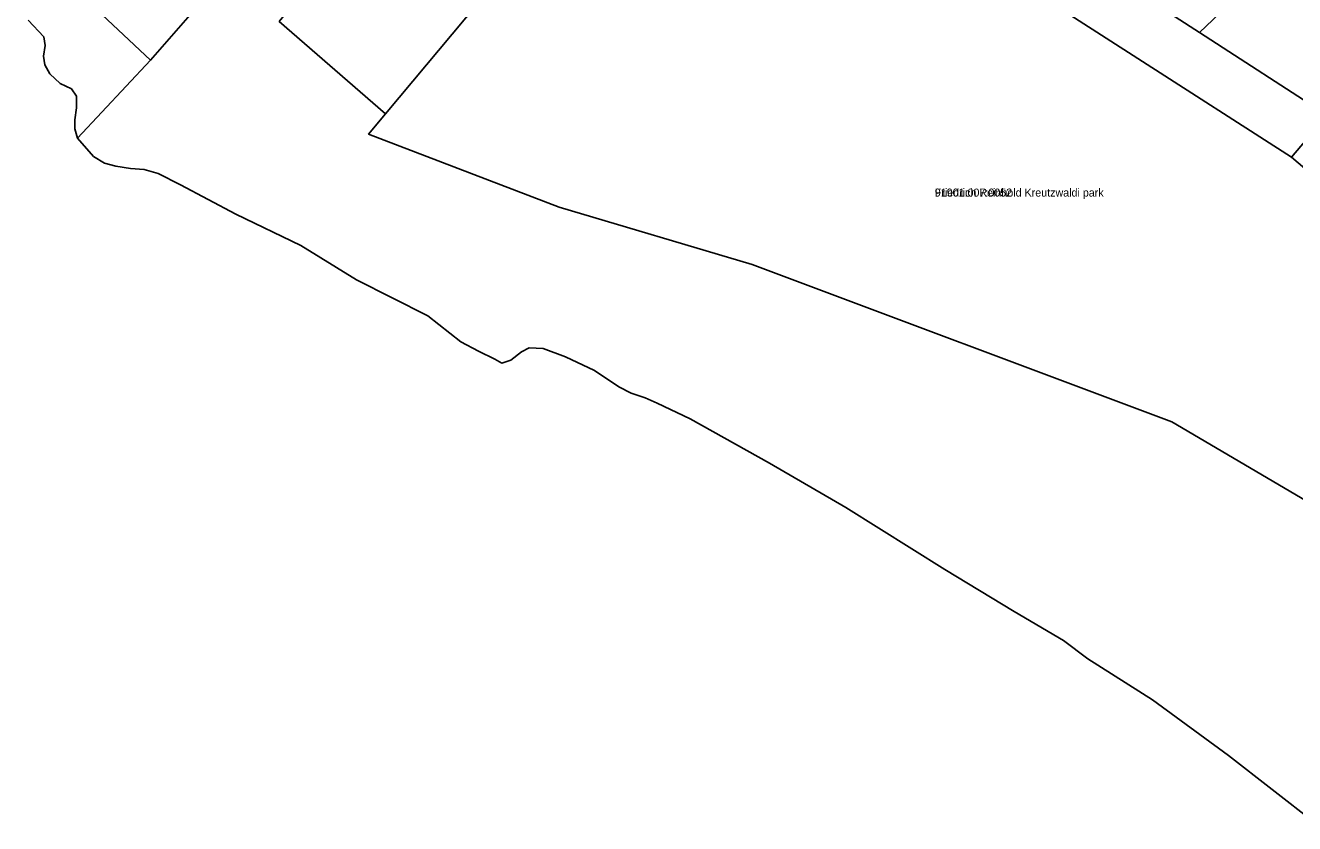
# Model space of a CAD drawing. Extents: x 675810 to 681273, y 6411190 to 6417565.
# Drawn here: x 677270.4 to 677508.4, y 6415331.4 to 6415481 of the extents above; entities that cross this region are included whole.
import ezdxf

# ---------------------------------------------------------------- set-up
doc = ezdxf.new("R2010")
doc.units = 0
for name, color, linetype in [('L_AADRESS', 7, 'Continuous'), ('PIIR', 7, 'Continuous'), ('TUNNUS', 7, 'Continuous')]:
    doc.layers.add(name, color=color, linetype=linetype)

msp = doc.modelspace()

# ---------------------------------------------------------------- linework, layer by layer
at = {"layer": 'PIIR'}
for points in [[(677619.3, 6415586.7), (677640.22, 6415568.39), (677619.9, 6415544.86), (677604, 6415528.75), (677527.68, 6415439.36), (677507.74, 6415456.28), (677514.44, 6415464.15), (677541.32, 6415495.69), (677551.91, 6415508.21), (677567.84, 6415526.77), (677572.82, 6415532.42), (677579.26, 6415540.06), (677605.9, 6415571.07)], [(677377.21, 6415550.75), (677395.17, 6415538.44), (677460.53, 6415498.36), (677473.16, 6415490.87), (677490.51, 6415479.64), (677514.44, 6415464.15), (677507.74, 6415456.28), (677392.53, 6415530.33), (677391.54, 6415531.46), (677372.02, 6415544.64)], [(677473.16, 6415490.87), (677508.91, 6415532.58), (677514.96, 6415526.92), (677510.82, 6415522.1), (677523.55, 6415511.07), (677490.51, 6415479.64)], [(677274.63, 6415492.53), (677270.38, 6415496.45), (677303.25, 6415531.9), (677313.36, 6415522.9), (677315.6, 6415520.9), (677301.23, 6415503.97), (677302.65, 6415496.91), (677308.39, 6415492.05), (677307.59, 6415490.8), (677306.11, 6415488.49), (677293.83, 6415474.44)], [(677392.53, 6415530.33), (677507.74, 6415456.28), (677527.68, 6415439.36), (677550.13, 6415420.31), (677564.99, 6415407.75), (677582.2, 6415400.99), (677554.69, 6415367.45), (677550.88, 6415368.11), (677485.36, 6415406.68), (677406.64, 6415436.15), (677370.49, 6415446.92), (677334.72, 6415460.59), (677337.9, 6415464.39), (677355.53, 6415485.48), (677358.99, 6415489.69), (677380.91, 6415516.25)], [(677490.51, 6415479.64), (677523.55, 6415511.07), (677541.32, 6415495.69), (677514.44, 6415464.15)], [(677334.97, 6415502.53), (677355.53, 6415485.48), (677337.9, 6415464.39), (677317.98, 6415481.72)]]:
    msp.add_lwpolyline(points, close=True, dxfattribs=at)
for points in [[(677274.63, 6415492.53), (677293.83, 6415474.44), (677280.17, 6415459.81), (677279.66, 6415461.59), (677279.64, 6415463.28), (677279.97, 6415465.54), (677279.96, 6415467.69), (677279.01, 6415469.1), (677276.93, 6415470.09), (677274.98, 6415471.91), (677274.01, 6415473.6), (677273.75, 6415475.22), (677274.12, 6415477.2), (677273.82, 6415478.83), (677270.93, 6415481.93)], [(677512.33, 6415331.37), (677495.96, 6415344.11), (677481.74, 6415354.58), (677469.58, 6415362.23), (677465.02, 6415365.68), (677455.79, 6415371.12), (677442.79, 6415379.02), (677424.19, 6415390.6), (677409.92, 6415398.9), (677395.04, 6415407.26), (677388.86, 6415410.2), (677386.6, 6415411.14), (677383.94, 6415412.05), (677381.64, 6415413.24), (677377.07, 6415416.32), (677371.67, 6415418.86), (677367.45, 6415420.41), (677364.84, 6415420.57), (677363.41, 6415419.79), (677361.38, 6415418.23), (677359.7, 6415417.65), (677358.38, 6415418.39), (677355.33, 6415419.89), (677352.05, 6415421.68), (677345.83, 6415426.52), (677332.49, 6415433.27), (677322.01, 6415439.74), (677309.81, 6415445.62), (677299.47, 6415451.11), (677295.25, 6415453.21), (677292.68, 6415453.95), (677290.09, 6415454.18), (677287.33, 6415454.58), (677285.2, 6415455.15), (677283.18, 6415456.41), (677280.17, 6415459.81), (677293.83, 6415474.44), (677306.11, 6415488.49)], [(677270.93, 6415481.93), (677273.82, 6415478.83), (677274.12, 6415477.2), (677273.75, 6415475.22), (677274.01, 6415473.6), (677274.98, 6415471.91), (677276.93, 6415470.09), (677279.01, 6415469.1), (677279.96, 6415467.69), (677279.97, 6415465.54), (677279.64, 6415463.28), (677279.66, 6415461.59), (677280.17, 6415459.81), (677283.18, 6415456.41), (677285.2, 6415455.15), (677287.33, 6415454.58), (677290.09, 6415454.18), (677292.68, 6415453.95), (677295.25, 6415453.21), (677299.47, 6415451.11), (677309.81, 6415445.62), (677322.01, 6415439.74), (677332.49, 6415433.27), (677345.83, 6415426.52), (677352.05, 6415421.68), (677355.33, 6415419.89), (677358.38, 6415418.39), (677359.7, 6415417.65), (677361.38, 6415418.23), (677363.41, 6415419.79), (677364.84, 6415420.57), (677367.45, 6415420.41), (677371.67, 6415418.86), (677377.07, 6415416.32), (677381.64, 6415413.24), (677383.94, 6415412.05), (677386.6, 6415411.14), (677388.86, 6415410.2), (677395.04, 6415407.26), (677409.92, 6415398.9), (677424.19, 6415390.6), (677442.79, 6415379.02), (677455.79, 6415371.12), (677465.02, 6415365.68), (677469.58, 6415362.23), (677481.74, 6415354.58), (677495.96, 6415344.11), (677512.33, 6415331.37)], [(677317.98, 6415481.72), (677337.9, 6415464.39), (677334.72, 6415460.59), (677370.49, 6415446.92), (677406.64, 6415436.15), (677485.36, 6415406.68), (677550.88, 6415368.11)]]:
    msp.add_lwpolyline(points, dxfattribs=at)

# ---------------------------------------------------------------- texts
at = {"layer": 'L_AADRESS'}
msp.add_text('Friedrich Reinhold Kreutzwaldi park', height=1.5, dxfattribs=at).set_placement((677440.89, 6415448.89))
at = {"layer": 'TUNNUS'}
msp.add_text('91901:007:0052', height=1.5, dxfattribs=at).set_placement((677440.89, 6415448.89))

doc.saveas('drawing.dxf')
